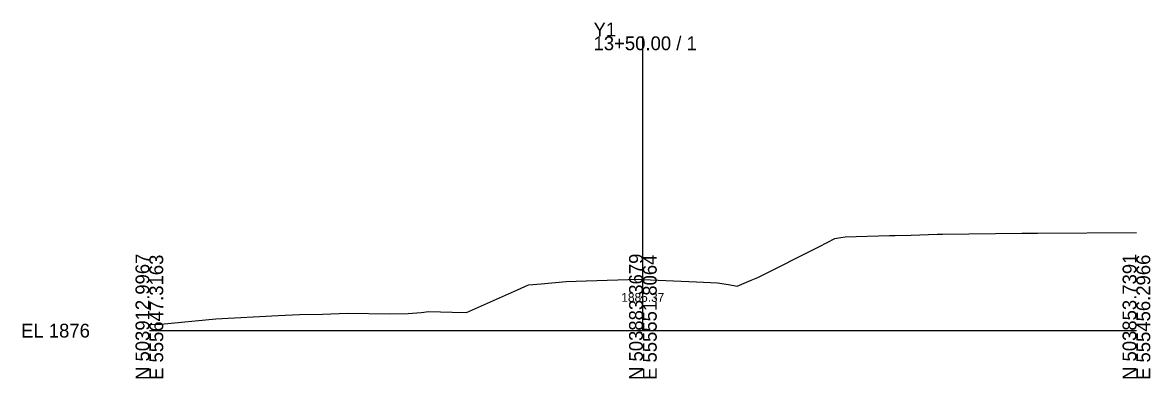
# Model space of a CAD drawing. Extents: x -26 to 1503, y -10 to 5015.
# Drawn here: x -25.7 to 202.8, y 3490.3 to 3562.4 of the extents above; entities that cross this region are included whole.
import ezdxf

# ---------------------------------------------------------------- set-up
doc = ezdxf.new("R2010")
doc.units = 0
for name, color, linetype in [('Default', 7, 'Continuous'), ('Exist Cross Section Cell', 7, 'Continuous'), ('Exist XS Center Line Elevation Label', 7, 'Continuous'), ('Exist XS Ground Line', 7, 'Continuous')]:
    doc.layers.add(name, color=color, linetype=linetype)

msp = doc.modelspace()

# ---------------------------------------------------------------- linework, layer by layer
at = {"layer": 'Exist Cross Section Cell'}
for p, q in [((100, 3500), (100, 3559.64)), ((0, 3500), (100, 3500)), ((100, 3500), (200, 3500))]:
    msp.add_line(p, q, dxfattribs=at)
at = {"layer": 'Exist XS Ground Line'}
for p, q in [((154.38, 3519.35), (159.61, 3519.54)), ((159.61, 3519.54), (160.71, 3519.54)), ((160.71, 3519.54), (176.8, 3519.75)), ((176.8, 3519.75), (179.96, 3519.77)), ((179.96, 3519.77), (200, 3519.88)), ((135.77, 3517.07), (138.89, 3518.65)), ((138.89, 3518.65), (140.1, 3518.87)), ((140.1, 3518.87), (140.98, 3519)), ((140.98, 3519), (149.99, 3519.27)), ((149.99, 3519.27), (151.13, 3519.3)), ((151.13, 3519.3), (154.38, 3519.35)), ((123.31, 3510.8), (135.77, 3517.07)), ((88.51, 3510.06), (99.2, 3510.41)), ((99.2, 3510.41), (100, 3510.37)), ((100, 3510.37), (110.83, 3509.86)), ((121.96, 3510.24), (123.31, 3510.8)), ((64.25, 3503.69), (74.59, 3508.27)), ((74.59, 3508.27), (76.83, 3509.26)), ((76.83, 3509.26), (79.36, 3509.47)), ((79.36, 3509.47), (84.42, 3509.93)), ((84.42, 3509.93), (88.51, 3510.06)), ((110.83, 3509.86), (115.15, 3509.72)), ((115.15, 3509.72), (117.35, 3509.32)), ((117.35, 3509.32), (119.13, 3508.98)), ((119.13, 3508.98), (121.96, 3510.24)), ((35.06, 3503.33), (40.12, 3503.54)), ((40.12, 3503.54), (48.7, 3503.4)), ((48.7, 3503.4), (52.45, 3503.45)), ((52.45, 3503.45), (55.05, 3503.69)), ((55.05, 3503.69), (56.63, 3503.91)), ((56.63, 3503.91), (61.37, 3503.74)), ((61.37, 3503.74), (64.25, 3503.69)), ((0, 3501.23), (2.35, 3501.34)), ((2.35, 3501.34), (13.46, 3502.42)), ((13.46, 3502.42), (26.13, 3503.05)), ((26.13, 3503.05), (30.41, 3503.25)), ((30.41, 3503.25), (35.06, 3503.33))]:
    msp.add_line(p, q, dxfattribs=at)

# ---------------------------------------------------------------- texts
at = {"layer": 'Default'}
msp.add_text('-', height=0.0001, dxfattribs=at).set_placement((0, 3500))
at = {"layer": 'Exist Cross Section Cell'}
for s, p in [('Y1', (90, 3559.64)), ('13+50.00 / 1', (90, 3556.84)), ('EL 1876', (-26, 3498.6))]:
    msp.add_text(s, height=2.8, dxfattribs=at).set_placement(p)
for s, p in [('N 503912.9967', (0, 3490)), ('E 555647.3163', (2.8, 3490)), ('N 503883.3679', (100, 3490)), ('E 555551.8064', (102.8, 3490)), ('N 503853.7391', (200, 3490)), ('E 555456.2966', (202.8, 3490))]:
    msp.add_text(s, height=2.8, rotation=90, dxfattribs=at).set_placement(p)
at = {"layer": 'Exist XS Center Line Elevation Label'}
msp.add_text('1886.37', height=1.8, dxfattribs=at).set_placement((95.63, 3505.84))

doc.saveas('drawing.dxf')
